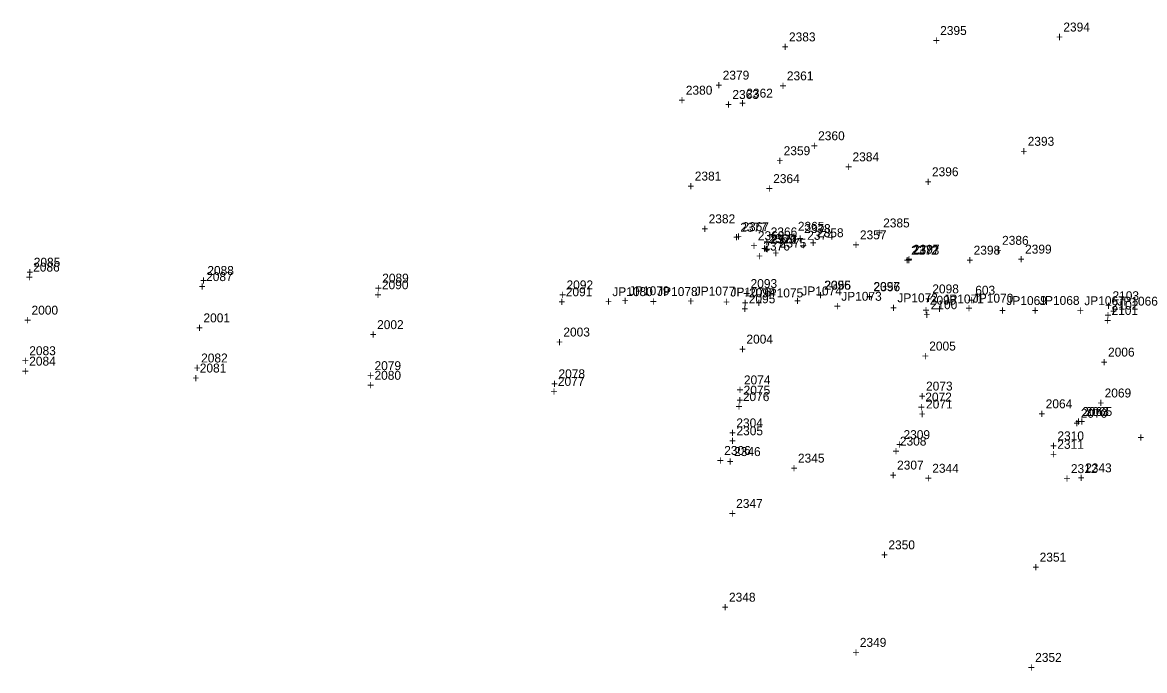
# Model space of a CAD drawing. Extents: x 2192192 to 2193475, y 863716 to 864270.
# Drawn here: x 2192192 to 2192506.3, y 863849.1 to 864030.6 of the extents above; entities that cross this region are included whole.
import ezdxf

# ---------------------------------------------------------------- set-up
doc = ezdxf.new("R2010")
doc.units = 0
for name, color, linetype in [('S_Control_Temp_Traverse', 7, 'Continuous'), ('S_Drainage_Culvert_Top', 7, 'Continuous'), ('S_Drainage_Ditch_Line', 7, 'Continuous'), ('S_Drainage_Invert', 7, 'Continuous'), ('S_Ground_Elevation', 7, 'Continuous'), ('S_Ground_LevelString', 7, 'Continuous'), ('S_Roadway_Centerline', 7, 'Continuous'), ('S_Roadway_Edge_Pavement', 7, 'Continuous'), ('S_Roadway_Edge_Shoulder', 7, 'Continuous'), ('S_Roadway_Edge_TW', 7, 'Continuous'), ('S_Roadway_Entr_Field_Wood', 7, 'Continuous'), ('S_Trees_TreeLine', 7, 'Continuous'), ('S_Utilities_UG_Telephone', 7, 'Continuous')]:
    doc.layers.add(name, color=color, linetype=linetype)

msp = doc.modelspace()

# ---------------------------------------------------------------- texts
at = {"layer": 'S_Control_Temp_Traverse'}
for s, p in [('603', (2192458.89, 863954.35)), ('603', (2192458.89, 863954.35)), ('603', (2192458.89, 863954.35)), ('+', (2192456.83, 863951.6)), ('+', (2192456.83, 863951.6)), ('+', (2192456.83, 863951.6))]:
    msp.add_text(s, height=2.5, dxfattribs=at).set_placement(p)
at = {"layer": 'S_Drainage_Culvert_Top'}
for s, p in [('2371', (2192401.7, 863968.6)), ('+', (2192399.63, 863965.85)), ('2372', (2192440.93, 863965.54)), ('+', (2192438.87, 863962.79))]:
    msp.add_text(s, height=2.5, dxfattribs=at).set_placement(p)
at = {"layer": 'S_Drainage_Ditch_Line'}
for s, p in [('2367', (2192393.67, 863972.14)), ('+', (2192391.61, 863969.39)), ('2368', (2192397.99, 863969.61)), ('2369', (2192400.96, 863968.8)), ('+', (2192395.93, 863966.86)), ('+', (2192398.89, 863966.05)), ('2397', (2192441.44, 863965.81)), ('2398', (2192458.44, 863965.56)), ('2399', (2192472.85, 863965.85)), ('+', (2192439.38, 863963.06)), ('+', (2192456.38, 863962.81)), ('+', (2192470.79, 863963.1)), ('2304', (2192391.98, 863917.19)), ('+', (2192389.92, 863914.44)), ('2305', (2192392.01, 863914.97)), ('2309', (2192438.8, 863913.9)), ('+', (2192389.95, 863912.22)), ('+', (2192436.74, 863911.15)), ('2308', (2192437.78, 863912.08)), ('2311', (2192481.87, 863911.18)), ('2310', (2192481.91, 863913.56)), ('+', (2192435.72, 863909.33)), ('+', (2192479.81, 863908.43)), ('+', (2192479.85, 863910.81))]:
    msp.add_text(s, height=2.5, dxfattribs=at).set_placement(p)
at = {"layer": 'S_Drainage_Invert'}
for s, p in [('2370', (2192401.42, 863968.69)), ('+', (2192399.36, 863965.94)), ('2373', (2192441.36, 863965.56)), ('+', (2192439.3, 863962.81))]:
    msp.add_text(s, height=2.5, dxfattribs=at).set_placement(p)
at = {"layer": 'S_Ground_Elevation'}
for s, p in [('2395', (2192449.07, 864027.07)), ('2394', (2192483.57, 864028.05)), ('2383', (2192406.72, 864025.28)), ('+', (2192447.01, 864024.32)), ('+', (2192481.51, 864025.3)), ('+', (2192404.66, 864022.53)), ('2380', (2192377.82, 864010.36)), ('2363', (2192390.87, 864009.17)), ('+', (2192375.76, 864007.61)), ('+', (2192388.81, 864006.42)), ('2393', (2192473.58, 863996.04)), ('+', (2192471.52, 863993.29)), ('2384', (2192424.52, 863991.69)), ('2381', (2192380.33, 863986.31)), ('+', (2192422.46, 863988.94)), ('2396', (2192446.77, 863987.52)), ('+', (2192378.27, 863983.56)), ('2364', (2192402.29, 863985.59)), ('+', (2192444.71, 863984.77)), ('+', (2192400.23, 863982.84)), ('2382', (2192384.22, 863974.34)), ('+', (2192382.16, 863971.59)), ('2366', (2192401.6, 863970.67)), ('2365', (2192409.2, 863972.24)), ('2385', (2192433.1, 863973.18)), ('+', (2192399.54, 863967.92)), ('2375', (2192404.14, 863967.55)), ('+', (2192407.14, 863969.49)), ('2374', (2192411.82, 863969.71)), ('+', (2192431.04, 863970.43)), ('2386', (2192466.41, 863968.31)), ('2376', (2192399.53, 863966.71)), ('+', (2192402.08, 863964.8)), ('+', (2192409.76, 863966.96)), ('+', (2192464.35, 863965.56)), ('+', (2192397.46, 863963.96)), ('2346', (2192391.35, 863909.15)), ('+', (2192389.28, 863906.4)), ('2345', (2192409.23, 863907.32)), ('2344', (2192446.85, 863904.47)), ('2343', (2192489.67, 863904.59)), ('+', (2192407.17, 863904.57)), ('+', (2192444.79, 863901.72)), ('+', (2192487.61, 863901.84)), ('2347', (2192391.93, 863894.63)), ('+', (2192389.87, 863891.88)), ('2350', (2192434.57, 863883.03)), ('+', (2192432.51, 863880.28)), ('2351', (2192476.94, 863879.58)), ('+', (2192474.88, 863876.83)), ('2348', (2192389.92, 863868.37)), ('+', (2192387.86, 863865.62)), ('2349', (2192426.56, 863855.72)), ('+', (2192424.5, 863852.97)), ('2352', (2192475.68, 863851.51)), ('+', (2192473.62, 863848.76))]:
    msp.add_text(s, height=2.5, dxfattribs=at).set_placement(p)
at = {"layer": 'S_Ground_LevelString'}
for s, p in [('2065', (2192489.82, 863920.37)), ('+', (2192487.76, 863917.62))]:
    msp.add_text(s, height=2.5, dxfattribs=at).set_placement(p)
at = {"layer": 'S_Roadway_Centerline'}
for s, p in [('2000', (2192194.55, 863948.76)), ('+', (2192192.49, 863946.01)), ('2001', (2192242.71, 863946.6)), ('+', (2192240.65, 863943.85)), ('2002', (2192291.35, 863944.7)), ('2003', (2192343.52, 863942.63)), ('+', (2192289.29, 863941.95)), ('+', (2192341.46, 863939.88)), ('2004', (2192394.8, 863940.65)), ('+', (2192392.74, 863937.9)), ('2005', (2192446.01, 863938.71)), ('2006', (2192496.09, 863937.01)), ('+', (2192443.95, 863935.96)), ('+', (2192494.03, 863934.26))]:
    msp.add_text(s, height=2.5, dxfattribs=at).set_placement(p)
at = {"layer": 'S_Roadway_Edge_Pavement'}
for s, p in [('2085', (2192195.18, 863962.19)), ('+', (2192193.12, 863959.44)), ('2088', (2192243.8, 863959.87)), ('+', (2192241.74, 863957.12)), ('2089', (2192292.78, 863957.73)), ('2092', (2192344.41, 863955.83)), ('+', (2192290.72, 863954.98)), ('+', (2192342.35, 863953.08)), ('2094', (2192395.55, 863953.63)), ('2099', (2192446.18, 863951.54)), ('+', (2192393.49, 863950.88)), ('+', (2192444.12, 863948.79)), ('2102', (2192497.16, 863950.18)), ('+', (2192495.1, 863947.43)), ('2084', (2192193.91, 863934.48)), ('+', (2192191.85, 863931.73)), ('2081', (2192241.68, 863932.55)), ('2080', (2192290.62, 863930.51)), ('+', (2192239.62, 863929.8)), ('+', (2192288.56, 863927.76)), ('2077', (2192341.99, 863928.81)), ('2075', (2192394.02, 863926.35)), ('+', (2192339.93, 863926.06)), ('2072', (2192444.9, 863924.42)), ('+', (2192391.96, 863923.6)), ('+', (2192442.83, 863921.67)), ('2064', (2192478.63, 863922.53)), ('2063', (2192488.88, 863920.38)), ('+', (2192476.57, 863919.78)), ('+', (2192486.82, 863917.63)), ('+', (2192504.31, 863913.15))]:
    msp.add_text(s, height=2.5, dxfattribs=at).set_placement(p)
at = {"layer": 'S_Roadway_Edge_Shoulder'}
for s, p in [('2093', (2192395.96, 863956.21)), ('2096', (2192416.59, 863955.78)), ('2097', (2192430.36, 863955.39)), ('2098', (2192446.87, 863954.71)), ('+', (2192393.89, 863953.46)), ('+', (2192414.53, 863953.03)), ('+', (2192428.3, 863952.64)), ('+', (2192444.8, 863951.96)), ('2103', (2192497.33, 863952.8)), ('+', (2192495.27, 863950.05)), ('2076', (2192393.8, 863924.54)), ('+', (2192391.74, 863921.79)), ('2071', (2192445.12, 863922.47)), ('+', (2192443.06, 863919.72)), ('2070', (2192488.45, 863919.87)), ('+', (2192486.39, 863917.12))]:
    msp.add_text(s, height=2.5, dxfattribs=at).set_placement(p)
at = {"layer": 'S_Roadway_Edge_TW'}
for s, p in [('2086', (2192195.01, 863960.81)), ('2087', (2192243.46, 863958.15)), ('+', (2192192.95, 863958.06)), ('+', (2192241.4, 863955.4)), ('2090', (2192292.7, 863955.87)), ('+', (2192290.64, 863953.12)), ('2091', (2192344.2, 863953.9)), ('2095', (2192395.46, 863951.94)), ('+', (2192342.14, 863951.15)), ('+', (2192393.4, 863949.19)), ('2100', (2192446.43, 863950.28)), ('2101', (2192497.06, 863948.67)), ('+', (2192444.37, 863947.53)), ('+', (2192495, 863945.92)), ('2083', (2192193.92, 863937.4)), ('+', (2192191.86, 863934.65)), ('2082', (2192242.06, 863935.36)), ('2079', (2192290.63, 863933.21)), ('+', (2192240, 863932.61)), ('+', (2192288.56, 863930.46)), ('2078', (2192342.16, 863930.94)), ('+', (2192340.09, 863928.19)), ('2074', (2192394.1, 863929.22)), ('2073', (2192445.11, 863927.5)), ('+', (2192392.04, 863926.47)), ('+', (2192443.05, 863924.75)), ('2069', (2192495.13, 863925.56)), ('+', (2192493.07, 863922.81))]:
    msp.add_text(s, height=2.5, dxfattribs=at).set_placement(p)
at = {"layer": 'S_Roadway_Entr_Field_Wood'}
for s, p in [('2361', (2192406.13, 864014.38)), ('+', (2192404.07, 864011.63)), ('2362', (2192394.77, 864009.53)), ('+', (2192392.71, 864006.78)), ('2360', (2192414.89, 863997.6)), ('2359', (2192405.23, 863993.41)), ('+', (2192412.83, 863994.85)), ('+', (2192403.17, 863990.66)), ('2358', (2192414.58, 863970.44)), ('+', (2192412.52, 863967.69)), ('2357', (2192426.59, 863969.85)), ('+', (2192424.52, 863967.1)), ('2355', (2192416.68, 863955.74)), ('2356', (2192430.42, 863955.31)), ('+', (2192414.62, 863952.99)), ('+', (2192428.36, 863952.56))]:
    msp.add_text(s, height=2.5, dxfattribs=at).set_placement(p)
at = {"layer": 'S_Trees_TreeLine'}
for s, p in [('2379', (2192388.16, 864014.57)), ('+', (2192386.1, 864011.82)), ('2377', (2192393.08, 863971.97)), ('2378', (2192410.96, 863971.61)), ('+', (2192391.02, 863969.22)), ('+', (2192408.9, 863968.86)), ('2306', (2192388.58, 863909.47)), ('+', (2192386.52, 863906.72)), ('2307', (2192437, 863905.37)), ('2312', (2192485.68, 863904.37)), ('+', (2192434.94, 863902.62)), ('+', (2192483.62, 863901.62))]:
    msp.add_text(s, height=2.5, dxfattribs=at).set_placement(p)
at = {"layer": 'S_Utilities_UG_Telephone'}
for s, p in [('JP1080', (2192357.23, 863953.94)), ('JP1079', (2192361.92, 863954.2)), ('JP1078', (2192369.8, 863953.97)), ('JP1077', (2192380.33, 863954.11)), ('JP1076', (2192390.33, 863953.84)), ('JP1075', (2192399.36, 863953.58)), ('JP1074', (2192410.2, 863954.14)), ('JP1073', (2192421.36, 863952.64)), ('JP1072', (2192437.09, 863952.21)), ('JP1071', (2192449.96, 863951.89)), ('JP1070', (2192458.22, 863952.11)), ('JP1068', (2192476.77, 863951.49)), ('+', (2192355.17, 863951.19)), ('+', (2192359.85, 863951.45)), ('+', (2192367.74, 863951.22)), ('+', (2192378.27, 863951.36)), ('+', (2192388.27, 863951.09)), ('+', (2192397.3, 863950.83)), ('+', (2192408.14, 863951.39)), ('+', (2192419.29, 863949.89)), ('+', (2192435.03, 863949.46)), ('+', (2192447.9, 863949.14)), ('+', (2192456.16, 863949.36)), ('JP1069', (2192467.62, 863951.44)), ('JP1067', (2192489.43, 863951.41)), ('JP1066', (2192498.71, 863951.28)), ('+', (2192465.56, 863948.69)), ('+', (2192474.71, 863948.74)), ('+', (2192487.36, 863948.66)), ('+', (2192496.65, 863948.53))]:
    msp.add_text(s, height=2.5, dxfattribs=at).set_placement(p)

doc.saveas('drawing.dxf')
